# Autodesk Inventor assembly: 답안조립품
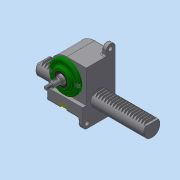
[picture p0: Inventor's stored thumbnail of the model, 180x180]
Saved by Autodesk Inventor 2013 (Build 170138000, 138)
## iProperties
Created: 2019-06
Part Number: 답안조립품
Document SubType Name: Assembly
Designer: Administrator
Mass: 3231.45 g
Surface Area: 1361.8 cm^2
Volume: 644.405 cm^3
Density: 5.01463 g/cm^3
Author: Administrator
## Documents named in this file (10)
- C:\Users\Administrator\Desktop\390604V1013\답안조립품.iam
- C:\Users\Administrator\Desktop\390604V1013\본체.ipt
- C:\Users\Administrator\Desktop\390604V1013\누름쇠.ipt
- C:\Users\Administrator\Desktop\390604V1013\뒤커버.ipt
- C:\Users\Administrator\Desktop\390604V1013\래크.ipt
- C:\Users\Administrator\Desktop\390604V1013\베어링 6003.ipt
- C:\Users\Administrator\Desktop\390604V1013\볼트 M4.ipt
- C:\Users\Administrator\Desktop\390604V1013\앞커버.ipt
- C:\Users\Administrator\Desktop\390604V1013\오일 실 17 30 5.ipt
- C:\Users\Administrator\Desktop\390604V1013\피니언.ipt
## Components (1 placed, 1 different names)
1. 피니언:1 — 각도:1
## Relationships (1: Angle 1)
- 각도:1 [Angle]: 피니언:1
